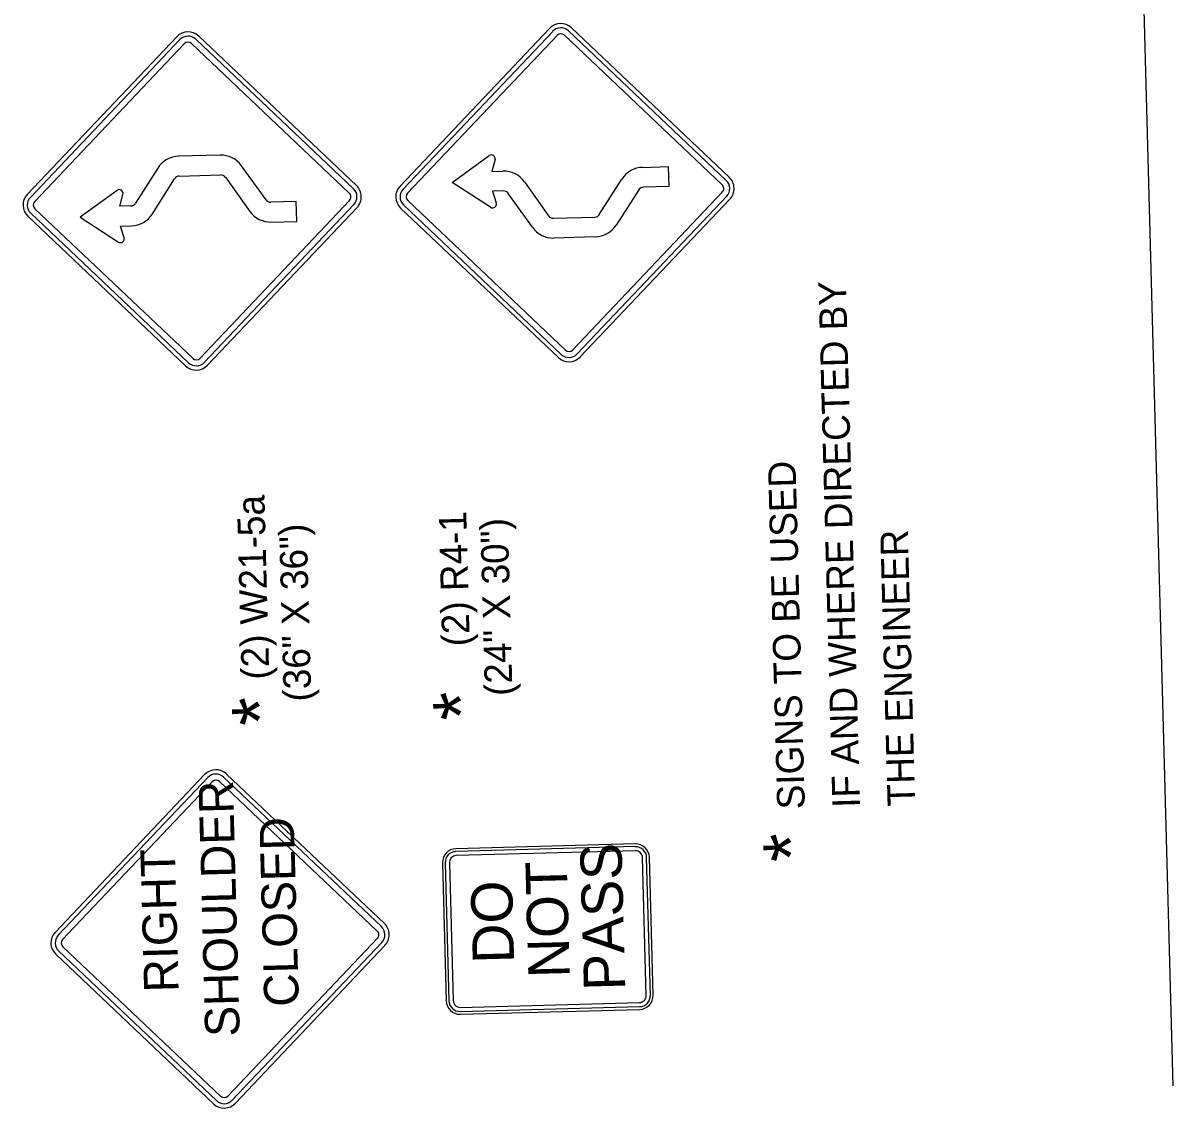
# Model space of a CAD drawing. Extents: x 1929653 to 1931621, y 596452 to 600944.
# Drawn here: x 1930580.1 to 1930830.1, y 599667.1 to 599903.1 of the extents above; entities that cross this region are included whole.
import ezdxf

# ---------------------------------------------------------------- set-up
doc = ezdxf.new("R2010")
doc.units = 0
for name, color, linetype in [('P_TC_Signs_Permanent', 7, 'Continuous'), ('P_TC_Signs_Temporary', 7, 'Continuous'), ('R_Border', 7, 'Continuous'), ('R_Draft', 7, 'Continuous'), ('S_AREA_CALC', 7, 'Continuous')]:
    doc.layers.add(name, color=color, linetype=linetype)

msp = doc.modelspace()

# ---------------------------------------------------------------- linework, layer by layer
at = {"layer": 'P_TC_Signs_Permanent'}
for p, q in [((1930713.16, 599724.56), (1930674.17, 599723.52)), ((1930713.18, 599723.97), (1930674.19, 599722.92)), ((1930713.2, 599723.07), (1930674.21, 599722.02)), ((1930715.55, 599691.62), (1930714.74, 599721.61)), ((1930716.45, 599691.64), (1930715.64, 599721.63)), ((1930717.05, 599691.66), (1930716.24, 599721.65)), ((1930671.26, 599720.44), (1930672.06, 599690.45)), ((1930671.86, 599720.46), (1930672.66, 599690.47)), ((1930672.76, 599720.48), (1930673.56, 599690.49)), ((1930675.1, 599689.03), (1930714.09, 599690.08)), ((1930675.12, 599688.13), (1930714.11, 599689.18)), ((1930675.14, 599687.53), (1930714.13, 599688.58))]:
    msp.add_line(p, q, dxfattribs=at)
for centre, radius, start, end in [((1930674.25, 599720.52), 3, 91.5377, 181.5377), ((1930713.24, 599721.57), 3, 1.5377, 91.5377), ((1930713.24, 599721.57), 2.4, 1.5377, 91.5377), ((1930674.25, 599720.52), 2.4, 91.5377, 181.5377), ((1930674.25, 599720.52), 1.5, 91.5377, 181.5377), ((1930713.24, 599721.57), 1.5, 1.5377, 91.5377), ((1930714.05, 599691.58), 1.5, 271.5377, 1.5377), ((1930714.05, 599691.58), 2.4, 271.5377, 1.5377), ((1930714.05, 599691.58), 3, 271.5377, 1.5377), ((1930675.06, 599690.53), 3, 181.5377, 271.5377), ((1930675.06, 599690.53), 2.4, 181.5377, 271.5377), ((1930675.06, 599690.53), 1.5, 181.5377, 271.5377)]:
    msp.add_arc(centre, radius, start, end, dxfattribs=at)
at = {"layer": 'P_TC_Signs_Temporary'}
for p, q in [((1930662.02, 599867.6), (1930694.52, 599901.9)), ((1930662.7, 599866.96), (1930695.21, 599901.25)), ((1930698.65, 599901.35), (1930732.95, 599868.84)), ((1930699.3, 599902.03), (1930733.59, 599869.53)), ((1930613.49, 599900.09), (1930580.98, 599865.8)), ((1930614.17, 599899.45), (1930581.66, 599865.15)), ((1930615.12, 599898.54), (1930582.62, 599864.25)), ((1930651, 599866.09), (1930616.71, 599898.59)), ((1930651.91, 599867.04), (1930617.61, 599899.54)), ((1930652.55, 599867.72), (1930618.26, 599900.22)), ((1930663.66, 599866.06), (1930696.16, 599900.35)), ((1930697.75, 599900.39), (1930732.04, 599867.89)), ((1930622.91, 599874.34), (1930613.9, 599874.09)), ((1930609.36, 599871.51), (1930604.53, 599863.86)), ((1930632.89, 599864.62), (1930627.56, 599872.03)), ((1930608.18, 599861.55), (1930613.02, 599869.2)), ((1930614.02, 599869.77), (1930623.02, 599870.02)), ((1930624.05, 599869.51), (1930629.39, 599862.09)), ((1930689.08, 599868.53), (1930694.32, 599861.15)), ((1930705.35, 599861.44), (1930710.28, 599869.13)), ((1930690.8, 599858.65), (1930685.56, 599866.03)), ((1930732.09, 599866.3), (1930699.58, 599832.01)), ((1930713.92, 599866.79), (1930708.99, 599859.11)), ((1930618.55, 599830.2), (1930651.05, 599864.49)), ((1930619.5, 599829.3), (1930652, 599863.59)), ((1930697.09, 599831.01), (1930662.8, 599863.51)), ((1930697.99, 599831.96), (1930663.7, 599864.47)), ((1930733.04, 599865.4), (1930700.54, 599831.1)), ((1930733.72, 599864.75), (1930701.22, 599830.46)), ((1930581.11, 599861.03), (1930615.41, 599828.52)), ((1930581.76, 599861.71), (1930616.05, 599829.2)), ((1930582.66, 599862.66), (1930616.95, 599830.16)), ((1930620.18, 599828.65), (1930652.68, 599862.95)), ((1930696.45, 599830.33), (1930662.15, 599862.83)), ((1930695.35, 599860.63), (1930704.35, 599860.88)), ((1930704.47, 599856.56), (1930695.47, 599856.31)), ((1930587.05, 599705.34), (1930619.55, 599739.64)), ((1930587.73, 599704.7), (1930620.23, 599738.99)), ((1930623.68, 599739.09), (1930657.97, 599706.58)), ((1930624.32, 599739.77), (1930658.62, 599707.26)), ((1930588.68, 599703.8), (1930621.18, 599738.09)), ((1930622.77, 599738.13), (1930657.07, 599705.63)), ((1930657.11, 599704.04), (1930624.61, 599669.75)), ((1930622.12, 599668.75), (1930587.82, 599701.25)), ((1930623.02, 599669.7), (1930588.72, 599702.2)), ((1930658.06, 599703.14), (1930625.56, 599668.84)), ((1930658.74, 599702.49), (1930626.24, 599668.2)), ((1930621.47, 599668.07), (1930587.18, 599700.57))]:
    msp.add_line(p, q, dxfattribs=at)
for points in [[(1930681.7, 599863.01), (1930673.38, 599868.4), (1930681.4, 599874.24)], [(1930682.68, 599873.36), (1930681.99, 599870.8), (1930684.41, 599870.86)], [(1930714.8, 599871.68), (1930720.35, 599871.83), (1930720.47, 599867.51), (1930714.92, 599867.36)], [(1930600.52, 599866.67), (1930592.49, 599860.84), (1930600.82, 599855.44)], [(1930603.53, 599863.29), (1930601.1, 599863.23), (1930601.79, 599865.79)], [(1930684.53, 599866.54), (1930682.1, 599866.48), (1930682.93, 599863.96)], [(1930634.04, 599859.79), (1930639.58, 599859.94), (1930639.47, 599864.26), (1930633.92, 599864.11)], [(1930602.05, 599856.39), (1930601.22, 599858.91), (1930603.64, 599858.97)]]:
    msp.add_lwpolyline(points, dxfattribs=at)
for centre, radius, start, end in [((1930615.94, 599897.77), 3.38, 46.5377, 136.5377), ((1930696.97, 599899.58), 3.37, 46.5377, 136.5377), ((1930696.97, 599899.58), 2.44, 46.5377, 136.5377), ((1930615.94, 599897.77), 2.44, 46.5377, 136.5377), ((1930615.94, 599897.77), 1.13, 46.5377, 136.5377), ((1930696.97, 599899.58), 1.13, 46.5377, 136.5377), ((1930614.05, 599868.55), 5.55, 91.5377, 147.7054), ((1930623.05, 599868.79), 5.55, 35.7539, 91.5377), ((1930681.88, 599873.57), 0.823, 344.8934, 126.0258), ((1930684.56, 599865.32), 5.55, 35.37, 91.5554), ((1930714.95, 599866.13), 5.55, 91.5377, 147.3215), ((1930614.05, 599868.55), 1.23, 91.5377, 147.7054), ((1930623.05, 599868.79), 1.23, 35.7539, 91.5377), ((1930731.27, 599867.08), 2.44, 316.5377, 46.5377), ((1930731.27, 599867.08), 3.38, 316.5377, 46.5377), ((1930583.43, 599863.48), 3.37, 136.5377, 226.5377), ((1930601, 599866.01), 0.823, 344.8934, 126.0258), ((1930650.23, 599865.27), 1.13, 316.5377, 46.5377), ((1930650.23, 599865.27), 2.44, 316.5377, 46.5377), ((1930650.23, 599865.27), 3.38, 316.5377, 46.5377), ((1930664.47, 599865.28), 3.37, 136.5377, 226.5377), ((1930664.47, 599865.28), 2.44, 136.5377, 226.5377), ((1930664.47, 599865.28), 1.13, 136.5377, 226.5377), ((1930684.56, 599865.32), 1.23, 35.37, 91.5554), ((1930714.95, 599866.13), 1.23, 91.5377, 147.3215), ((1930731.27, 599867.08), 1.13, 316.5377, 46.5377), ((1930583.43, 599863.48), 2.44, 136.5377, 226.5377), ((1930583.43, 599863.48), 1.13, 136.5377, 226.5377), ((1930603.49, 599864.52), 1.23, 271.52, 327.7054), ((1930633.89, 599865.34), 1.23, 215.7539, 271.5377), ((1930682.15, 599863.7), 0.823, 237.0496, 18.182), ((1930603.49, 599864.52), 5.55, 271.52, 327.7054), ((1930633.89, 599865.34), 5.55, 215.7539, 271.5377), ((1930695.32, 599861.86), 1.23, 215.37, 271.5377), ((1930704.32, 599862.1), 1.23, 271.5377, 327.3215), ((1930695.32, 599861.86), 5.55, 215.37, 271.5377), ((1930704.32, 599862.1), 5.55, 271.5377, 327.3215), ((1930601.26, 599856.13), 0.823, 237.0496, 18.182), ((1930698.77, 599832.78), 2.44, 226.5377, 316.5377), ((1930698.77, 599832.78), 1.13, 226.5377, 316.5377), ((1930617.73, 599830.97), 3.38, 226.5377, 316.5377), ((1930617.73, 599830.97), 2.44, 226.5377, 316.5377), ((1930617.73, 599830.97), 1.13, 226.5377, 316.5377), ((1930698.77, 599832.78), 3.38, 226.5377, 316.5377), ((1930622, 599737.32), 3.38, 46.5377, 136.5377), ((1930622, 599737.32), 2.44, 46.5377, 136.5377), ((1930622, 599737.32), 1.12, 46.5377, 136.5377), ((1930656.29, 599704.81), 2.44, 316.5377, 46.5377), ((1930656.29, 599704.81), 3.38, 316.5377, 46.5377), ((1930589.5, 599703.02), 3.38, 136.5377, 226.5377), ((1930589.5, 599703.02), 2.44, 136.5377, 226.5377), ((1930589.5, 599703.02), 1.13, 136.5377, 226.5377), ((1930656.29, 599704.81), 1.13, 316.5377, 46.5377), ((1930623.79, 599670.52), 2.44, 226.5377, 316.5377), ((1930623.79, 599670.52), 1.12, 226.5377, 316.5377), ((1930623.79, 599670.52), 3.38, 226.5377, 316.5377)]:
    msp.add_arc(centre, radius, start, end, dxfattribs=at)
at = {"layer": 'R_Draft'}
msp.add_line((1930830.07, 599671.93), (1930818.42, 600105.78), dxfattribs=at)

# ---------------------------------------------------------------- texts
at = {"layer": 'P_TC_Signs_Permanent'}
for s, rotation, p in [('PASS', 91.5377, (1930711.01, 599692.79)), ('NOT', 91.4973, (1930698.93, 599695.52)), ('DO', 91.5377, (1930686.85, 599698.68))]:
    msp.add_text(s, height=9, rotation=rotation, dxfattribs=at).set_placement(p)
at = {"layer": 'P_TC_Signs_Temporary'}
for s, p in [('SHOULDER', (1930627.19, 599682.73)), ('CLOSED', (1930640.04, 599689.26)), ('RIGHT', (1930613.9, 599692.4))]:
    msp.add_text(s, height=7.5, rotation=91.5377, dxfattribs=at).set_placement(p)
at = {"layer": 'R_Border'}
for s, p in [('IF AND WHERE DIRECTED BY', (1930762.04, 599732.5)), ('SIGNS TO BE USED', (1930750.04, 599732.18)), ('(2) W21-5a', (1930633.61, 599760.37)), ('(2) R4-1', (1930677.2, 599767.59)), ('(36" X 36")', (1930642.75, 599755.6)), ('(24" X 30")', (1930686.49, 599756.82)), ('THE ENGINEER', (1930774.03, 599732.82))]:
    msp.add_text(s, height=6, rotation=91.5377, dxfattribs=at).set_placement(p)
at = {"layer": 'S_AREA_CALC'}
for p in [(1930637.57, 599750.48), (1930681.31, 599751.65), (1930753.07, 599720.87)]:
    msp.add_text('*', height=12, rotation=91.5377, dxfattribs=at).set_placement(p)

doc.saveas('drawing.dxf')
